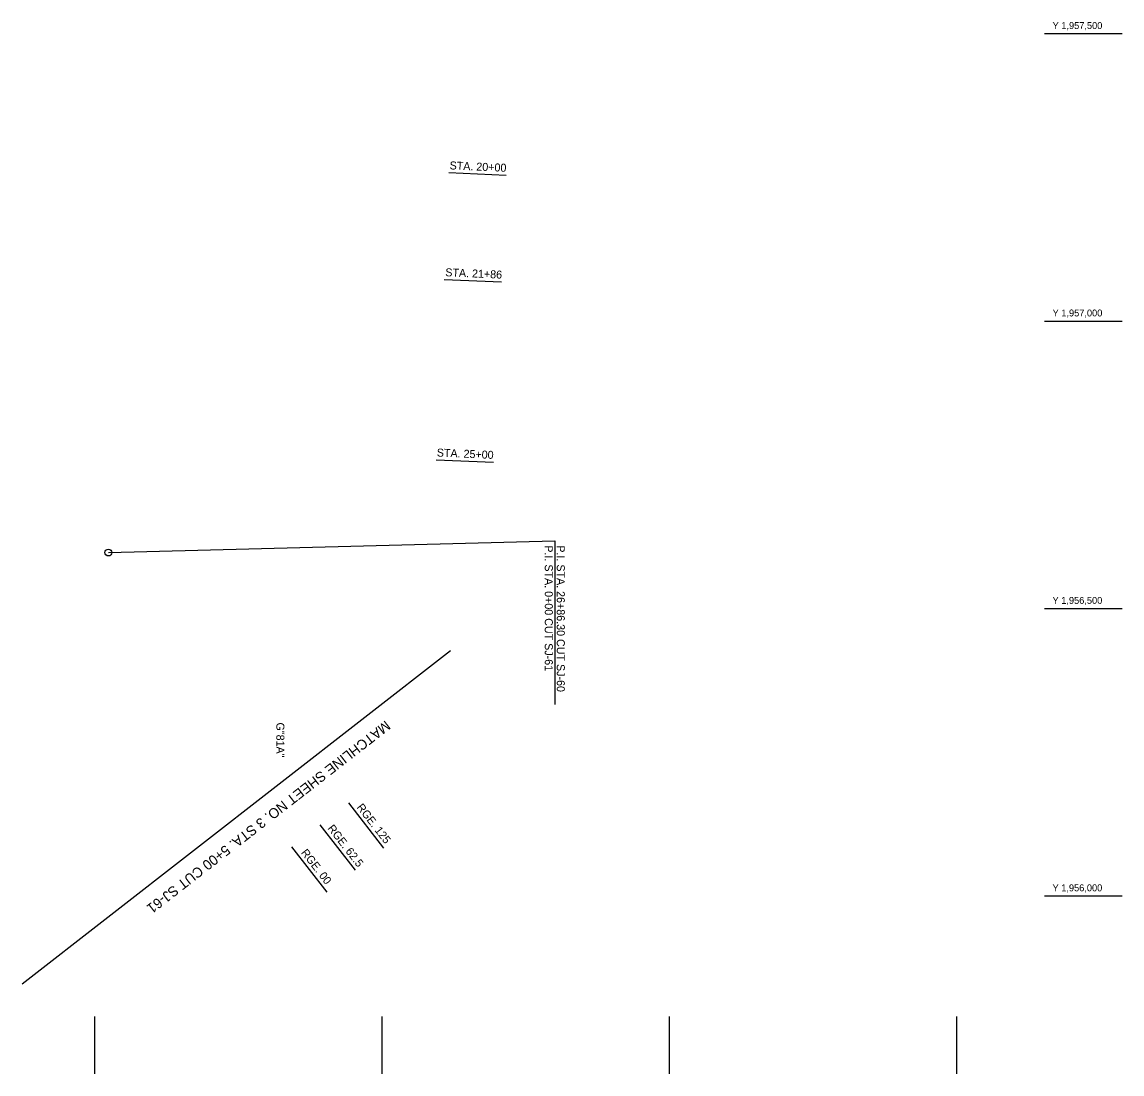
# Model space of a CAD drawing. Extents: x 576588 to 579788, y 1955489 to 1959590.
# Drawn here: x 577874 to 579788, y 1955690 to 1957520 of the extents above; entities that cross this region are included whole.
import ezdxf

# ---------------------------------------------------------------- set-up
doc = ezdxf.new("R2010")
doc.units = 0
for name, color, linetype in [('V-ANNO-KEYN', 7, 'Continuous'), ('V-ANNO-MASK', 7, 'Continuous'), ('V-ANNO-NOTE', 7, 'Continuous'), ('V-ANNO-NPLT', 7, 'Continuous'), ('V-ANNO-TEXT', 7, 'Continuous'), ('V-DUCT-MULT', 7, 'Continuous')]:
    doc.layers.add(name, color=color, linetype=linetype)

msp = doc.modelspace()

# ---------------------------------------------------------------- linework, layer by layer
at = {"layer": 'V-ANNO-KEYN'}
msp.add_line((577874, 1955847.3), (578619.5, 1956426.9), dxfattribs=at)
at = {"layer": 'V-ANNO-NOTE'}
for p, q in [((578441.8, 1956162), (578503.1, 1956083)), ((578392.4, 1956123.6), (578453.8, 1956044.7)), ((578343.1, 1956085.3), (578404.4, 1956006.3))]:
    msp.add_line(p, q, dxfattribs=at)
at = {"layer": 'V-ANNO-NPLT'}
for p, q in [((578616.4, 1957258.2), (578716.3, 1957253.7)), ((578608.2, 1957072.3), (578708.1, 1957067.9)), ((578594.3, 1956758.7), (578694.2, 1956754.2)), ((578024.2, 1956597.3), (578800.9, 1956617.5)), ((578800.9, 1956617.5), (578800.9, 1956333))]:
    msp.add_line(p, q, dxfattribs=at)
msp.add_circle((578024.2, 1956597.3), 6, dxfattribs=at)
at = {"layer": 'V-DUCT-MULT'}
for p, q in [((579652.8, 1957500), (579787.8, 1957500)), ((579652.8, 1957000), (579787.8, 1957000)), ((579652.8, 1956500), (579787.8, 1956500)), ((579652.8, 1956000), (579787.8, 1956000)), ((578000, 1955790.2), (578000, 1955690.2)), ((578500, 1955790.2), (578500, 1955690.2)), ((579000, 1955790.2), (579000, 1955690.2)), ((579500, 1955790.2), (579500, 1955690.2))]:
    msp.add_line(p, q, dxfattribs=at)

# ---------------------------------------------------------------- texts
at = {"layer": 'V-ANNO-MASK'}
msp.add_text('MATCHLINE SHEET NO. 3 STA. 5+00 CUT SJ-61', height=17.52, rotation=217.8605, dxfattribs=at).set_placement((578506.2, 1956306))
at = {"layer": 'V-ANNO-NOTE'}
for s, rotation, p in [('G"81A"', 270, (578316.5, 1956301.6)), ('RGE. 125', 307.8605, (578455.6, 1956153.9)), ('RGE. 62.5', 307.8605, (578404.9, 1956117.3)), ('RGE. 00', 307.8605, (578358.7, 1956074.9))]:
    msp.add_text(s, height=13.92, rotation=rotation, dxfattribs=at).set_placement(p)
at = {"layer": 'V-ANNO-NPLT'}
for s, rotation, p in [('STA. 20+00', 357.4686, (578617.7, 1957263.9)), ('STA. 21+86', 357.4686, (578610.2, 1957078)), ('STA. 25+00', 357.4686, (578595.4, 1956764.4)), ('P.I. STA. 0+00 CUT SJ-61', 270, (578783.5, 1956609.8)), ('P.I. STA. 26+86.30 CUT SJ-60', 270, (578804.4, 1956609.8))]:
    msp.add_text(s, height=13.92, rotation=rotation, dxfattribs=at).set_placement(p)
at = {"layer": 'V-ANNO-TEXT'}
for s, p in [('Y 1,957,500', (579667, 1957508)), ('Y 1,957,000', (579667, 1957008)), ('Y 1,956,500', (579666.9, 1956508)), ('Y 1,956,000', (579666.9, 1956008))]:
    msp.add_text(s, height=12, dxfattribs=at).set_placement(p)

doc.saveas('drawing.dxf')
